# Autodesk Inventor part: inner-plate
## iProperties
Shininess: 64.0
Length Units: 11269
Angle Units: 11279
Time Units: 11290
Mass Units: 11283
Length Display Precision: 3
Angle Display Precision: 2
Compacted: True
Part Number: inner-plate
Document SubType Name: Modeling
Created: 2003-11
Designer: Owner
Manufacturer: Standard
Standards Organization: Custom
Density: 1 g/cm^3
Density: 0.0
Volumn: 0.0
Area: 0.0
PropertySet Name: Model Information
Control State: 0
Master: False
Checked Out: False
Author: Owner
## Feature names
1. Extrusion1
